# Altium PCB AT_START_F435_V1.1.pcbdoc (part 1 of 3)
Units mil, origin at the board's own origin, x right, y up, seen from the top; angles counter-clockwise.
Board outline 6521.81 x 4041.5 mil, 2 copper layers (Top Layer, Bottom Layer); 158 components, 212 nets, 714 pads, 868 vias.
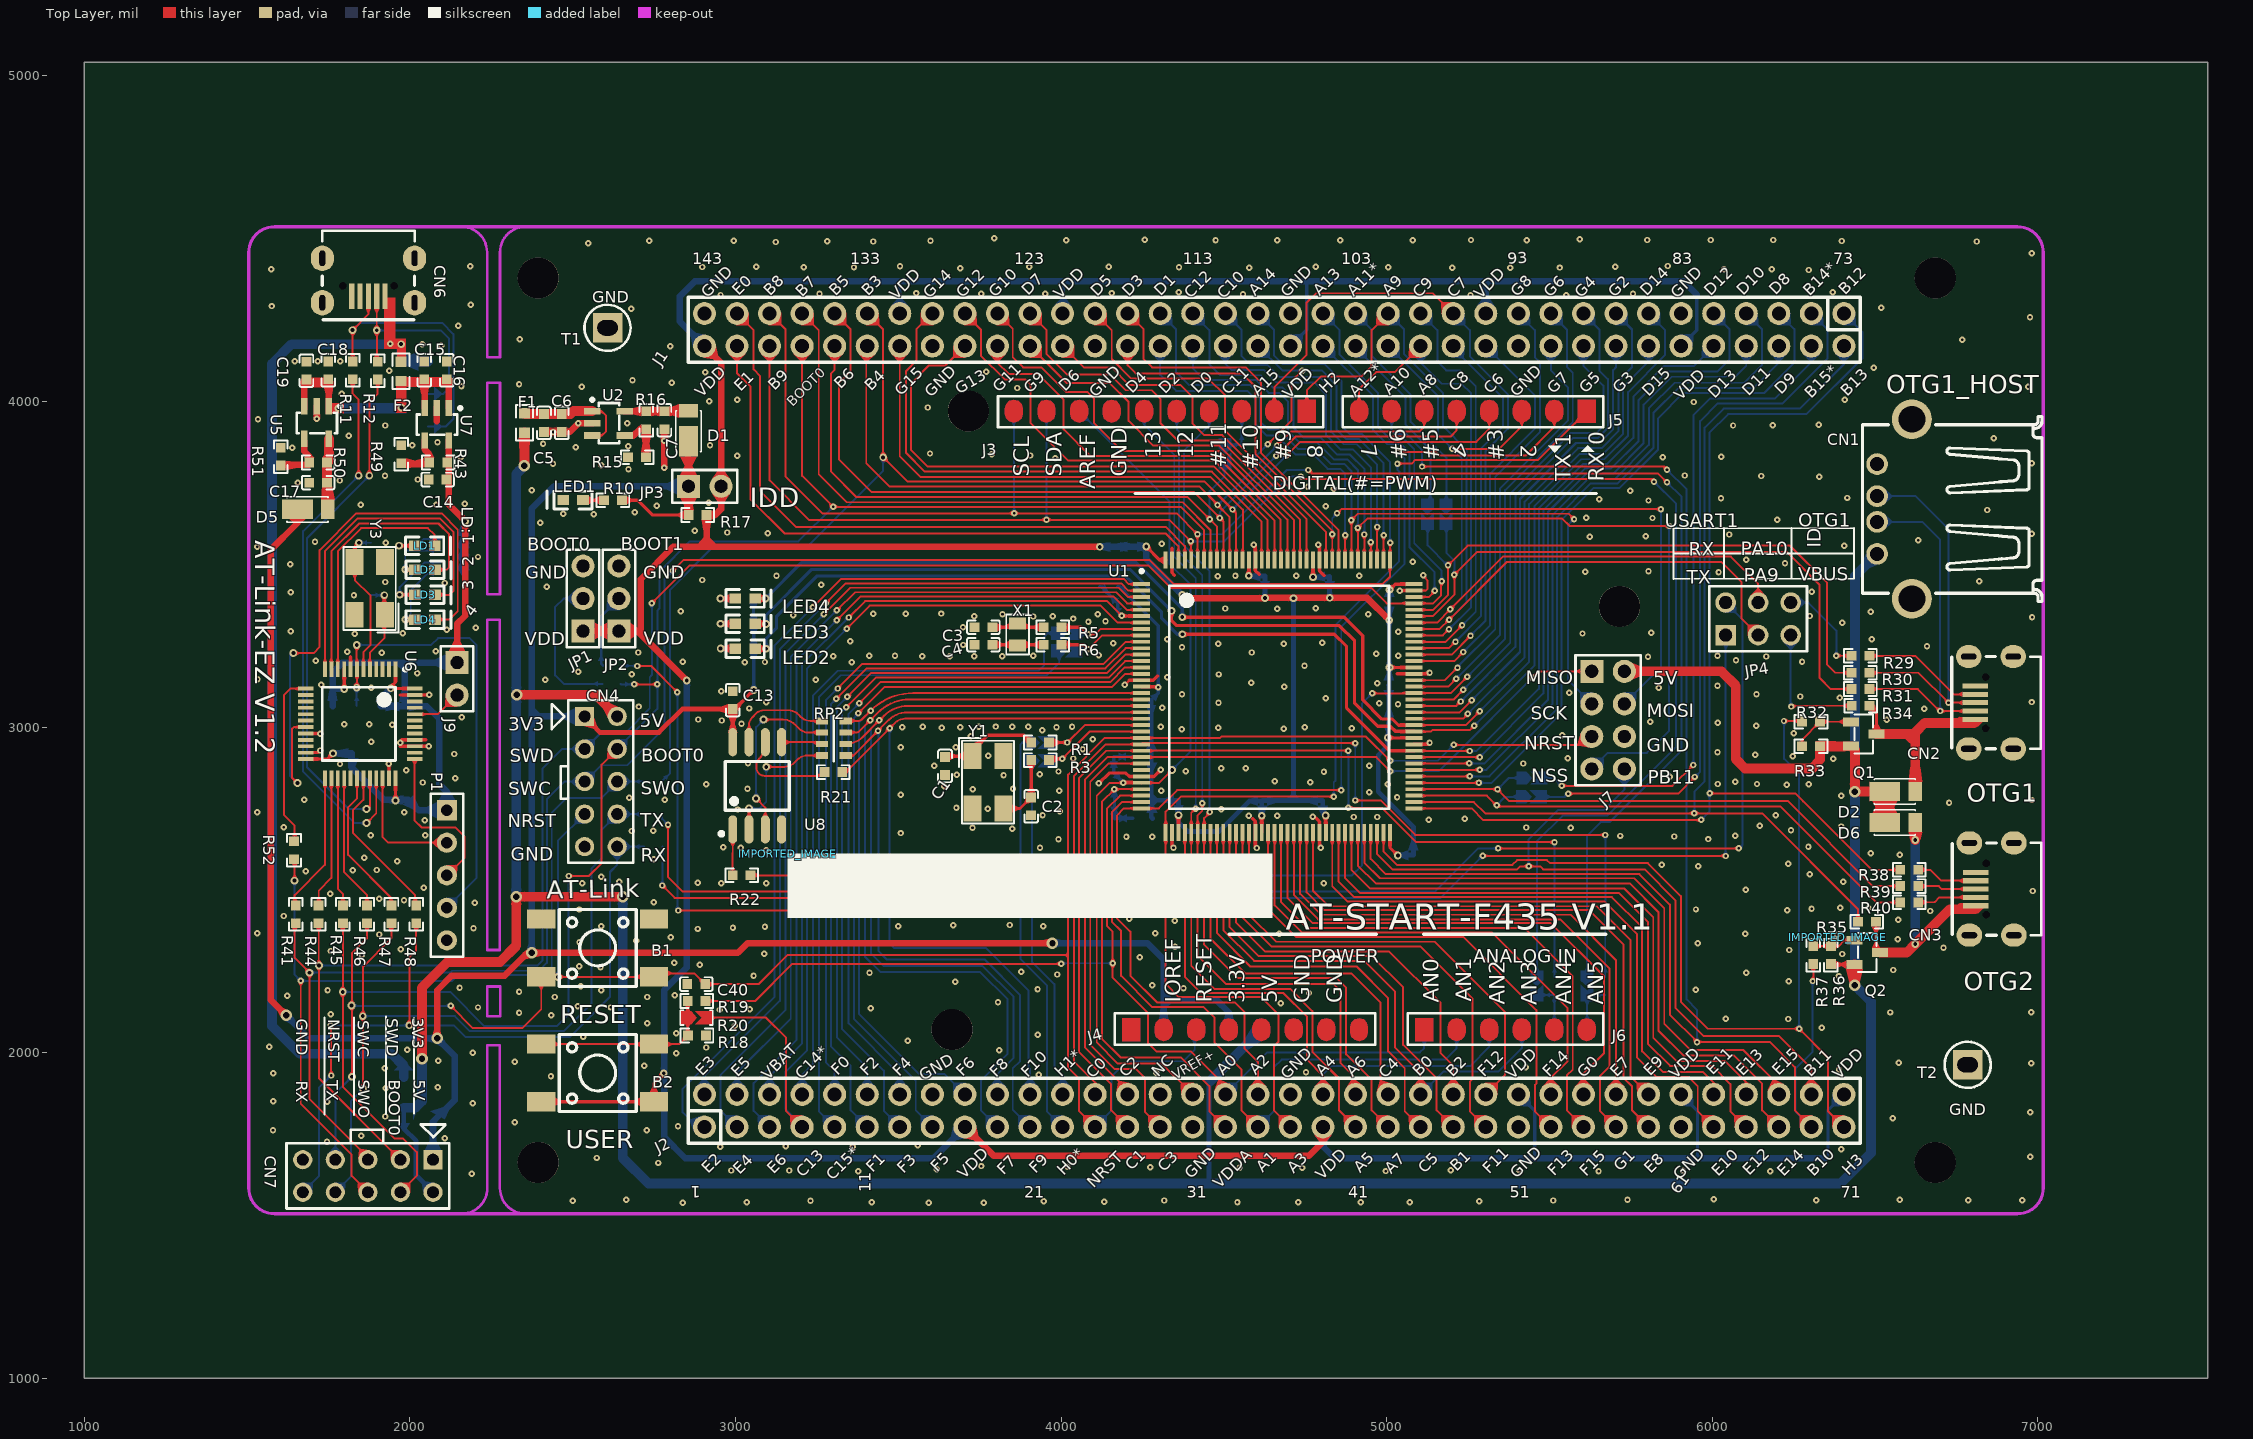
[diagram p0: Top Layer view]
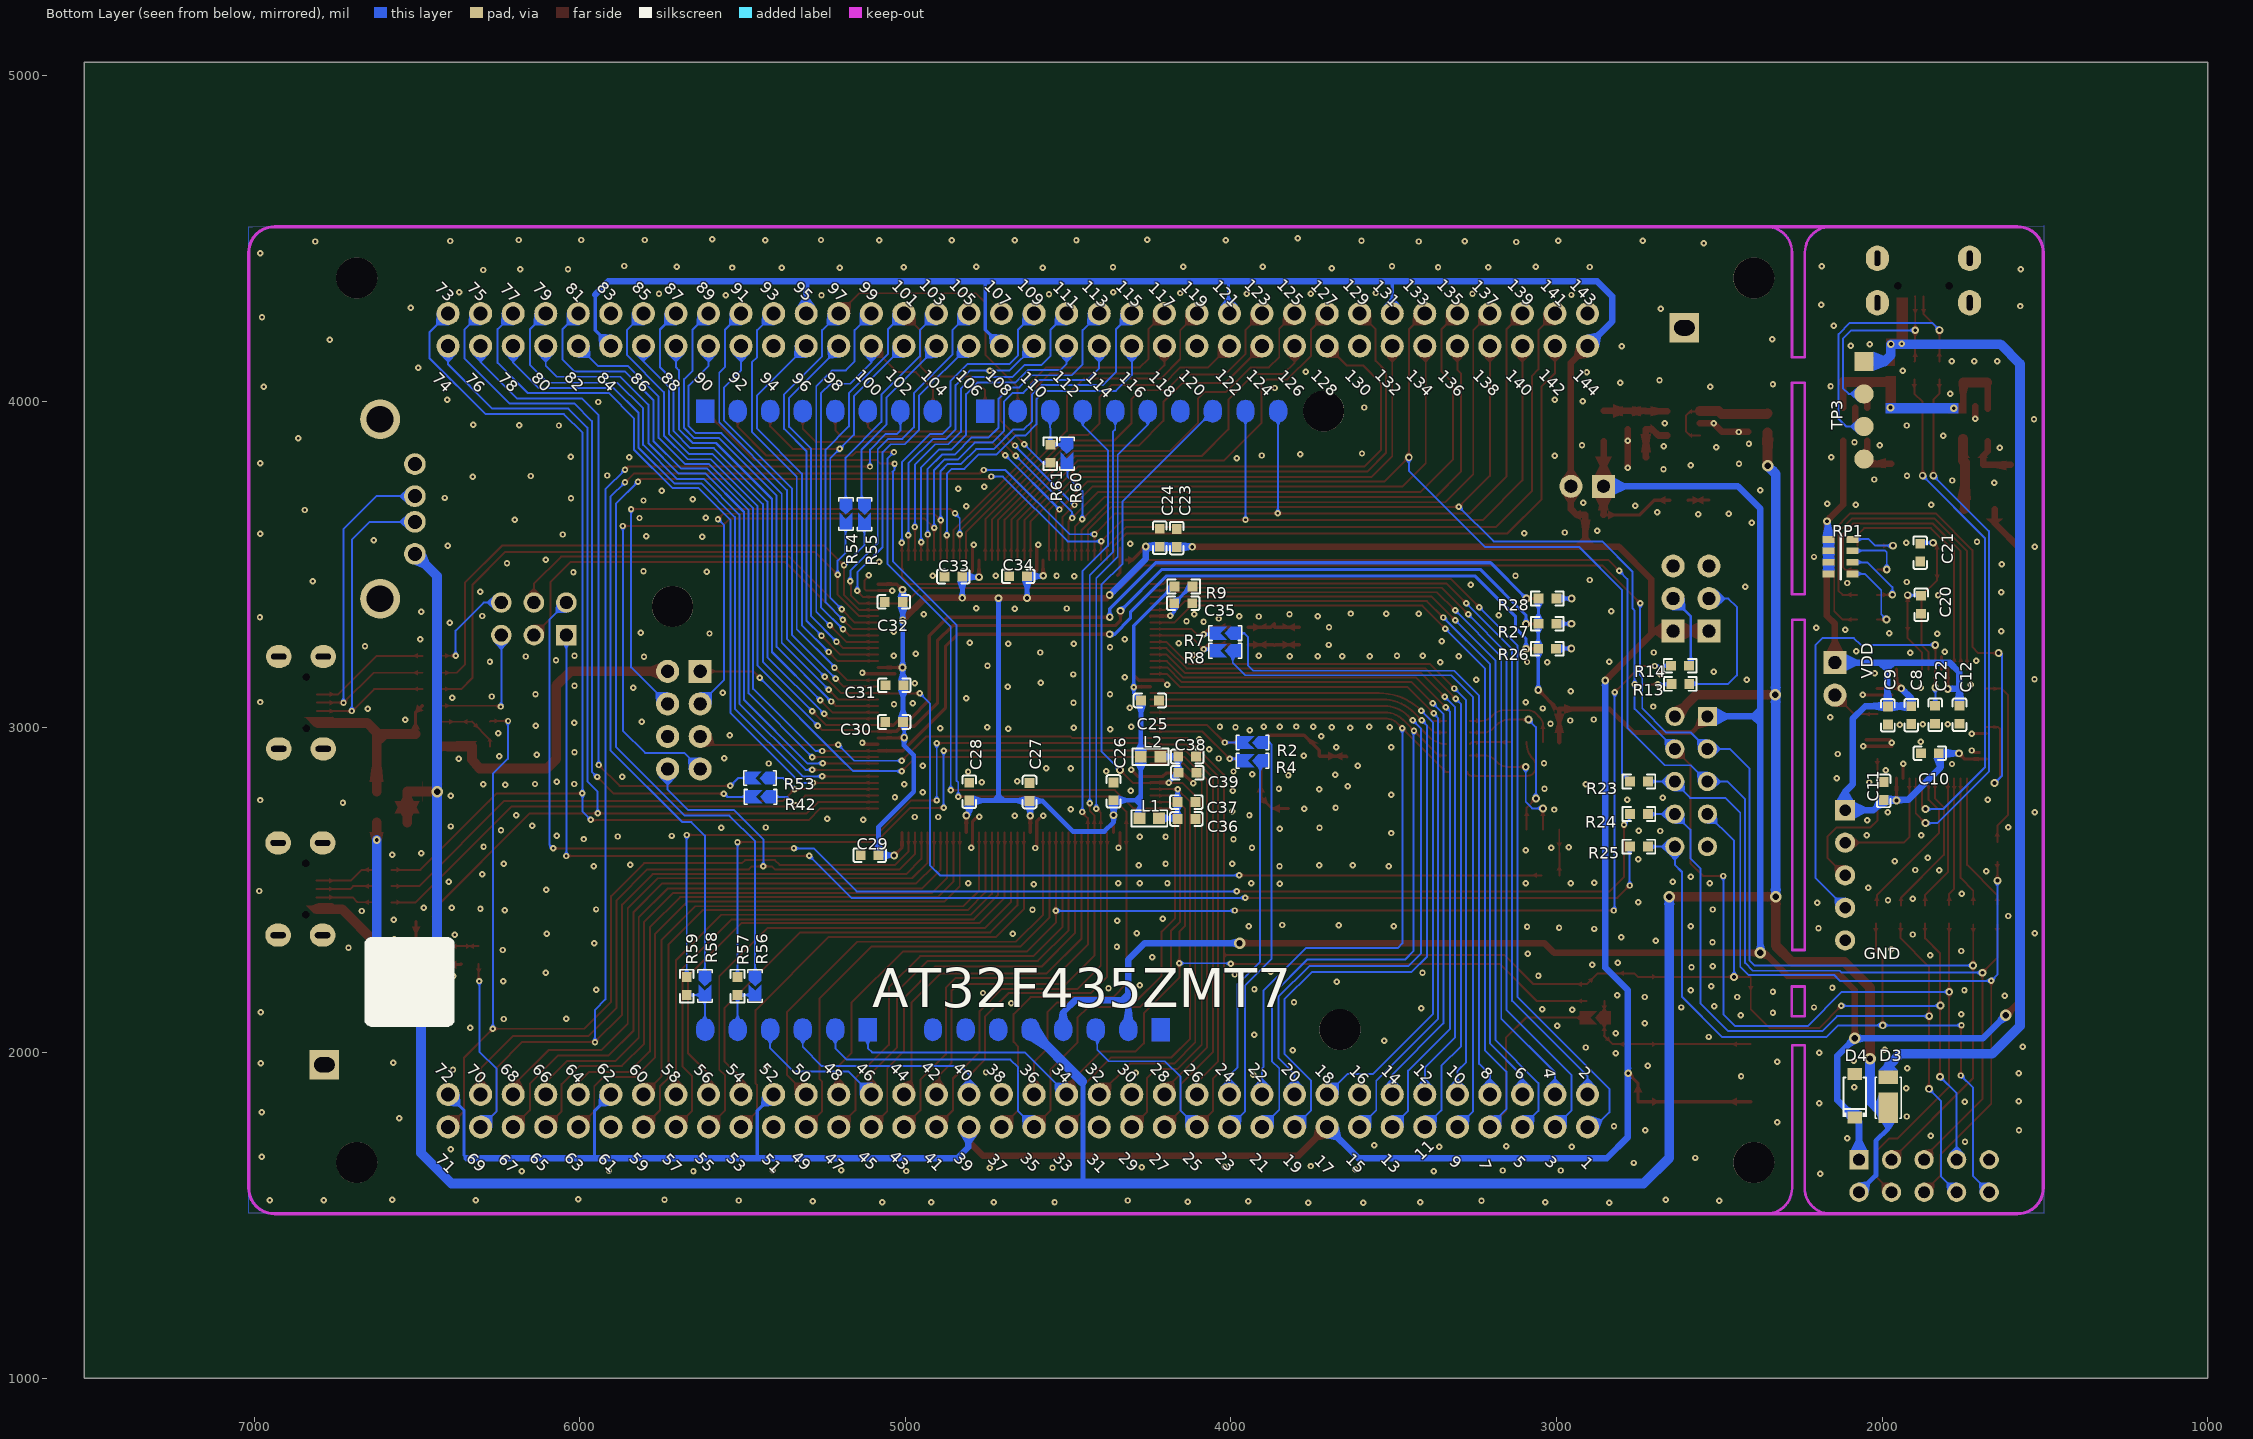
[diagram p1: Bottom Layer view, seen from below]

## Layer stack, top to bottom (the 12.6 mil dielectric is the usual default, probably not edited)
Top Layer: signal copper (thickness not stored)
Dielectric: dielectric 12.6, FR-4, Dk 4.8
Bottom Layer: signal copper (thickness not stored)

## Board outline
7521.81,1000 1000,1000 1000,5041.5 7521.81,5041.5

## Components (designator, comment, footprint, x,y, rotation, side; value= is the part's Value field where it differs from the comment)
B1 "贴片按键 6x6x5mm 黑色" SW-SMD_4P-L6.0-W6.0-P4.50-LS9.0 2576.69,2321.36 r180 top
B2 "贴片按键 6x6x5mm 蓝色" SW-SMD_4P-L6.0-W6.0-P4.50-LS9.0 2576.69,1937.36 r180 top
C1 "22pF" 0603_C-M#1 3643.64,2880.35 r270 top
C2 "22pF" 0603_C-M#1 3908.05,2756.34 r270 top
C3 "10pF" 0603_C-M#1 3761.68,3306.57 r180 top
C4 "10pF" 0603_C-M#1 3761.68,3252.78 r180 top
C5 "10uF" 0603_C-M#1 2411.64,3934 r90 top
C6 "0.1uF" 0603_C-M#1 2466.64,3934 r90 top
C7 "10uF" 0603_C-M#1 2781.64,3942.35 r90 top
C8 "4.7uF" 0603_C-M#2 1910.09,3036.57 r270 bottom
C9 "0.1uF" 0603_C-M#2 1982.09,3035.57 r270 bottom
C10 "0.1uF" 0603_C-M#2 1853.09,2919.57 r0 bottom
C11 "0.1uF" 0603_C-M#2 1995.09,2803.57 r90 bottom
C12 "0.1uF" 0603_C-M#2 1762.09,3037.57 r270 bottom
C13 "0.1uF" 0603_C-M#1 2991.55,3082.51 r270 top
C14 "10uF" 0603_C-M#1 2085,3760 r0 top
C15 "10uF" 0603_C-M#1 2044.09,4095.57 r270 top
C16 "0.1uF" 0603_C-M#1 2113.09,4095.57 r270 top
C17 "10uF" 0603_C-M#1 1718.09,3750.57 r0 top
C18 "10uF" 0603_C-M#1 1749.09,4095.57 r270 top
C19 "0.1uF" 0603_C-M#1 1682.09,4094.57 r270 top
C20 "22pF" 0603_C-M#2 1880.09,3375.57 r270 bottom
C21 "22pF" 0603_C-M#2 1883.09,3535.57 r90 bottom
C22 "0.1uF" 0603_C-M#2 1837.09,3037.57 r270 bottom
C23 "4.7uF" 0603_C-M#2 4166.64,3580.35 r90 bottom
C24 "0.1uF" 0603_C-M#2 4218.64,3581.35 r90 bottom
C25 "0.1uF" 0603_C-M#2 4248.64,3081.35 r180 bottom
C26 "0.1uF" 0603_C-M#2 4360.64,2802.35 r90 bottom
C27 "0.1uF" 0603_C-M#2 4618.64,2800.35 r90 bottom
C28 "0.1uF" 0603_C-M#2 4803.64,2801.35 r90 bottom
C29 "0.1uF" 0603_C-M#2 5109.64,2606.35 r0 bottom
C30 "0.1uF" 0603_C-M#2 5034.64,3015.35 r0 bottom
C31 "0.1uF" 0603_C-M#2 5033.64,3128.35 r0 bottom
C32 "0.1uF" 0603_C-M#2 5035.64,3384.35 r0 bottom
C33 "0.1uF" 0603_C-M#2 4852.64,3462.35 r0 bottom
C34 "0.1uF" 0603_C-M#2 4653.64,3463.35 r0 bottom
C35 "0.1uF" 0603_C-M#2 4146.64,3380.35 r180 bottom
C36 "1uF" 0603_C-M#2 4136.64,2717.35 r180 bottom
C37 "0.1uF" 0603_C-M#2 4136.64,2769.35 r180 bottom
C38 "0.1uF" 0603_C-M#2 4133.64,2859.35 r180 bottom
C39 "1uF" 0603_C-M#2 4134.64,2909.35 r180 bottom
C40 "0.1uF" 0603_C-M#1 2879.64,2210.35 r0 top
CN1 "JTJ-USB-AF-08" USB-A-TH__USB-AF-90 6560.06,3669.64 r90 top
CN2 "USB_micro B" USB_MIC_DIP 6807.49,3074.7 r0 top
CN3 "USB_micro B" USB_MIC_DIP 6809.35,2502.31 r0 top
CN4 "直插简易牛角2.54mm，2x5P" HDR2X5 2536.53,3032.54 r270 top
CN6 "USB_micro B" USB_MIC_DIP 1872.64,4322.58 r90 top
CN7 "直插简易牛角2.54mm，2x5P" HDR2X5 2070.89,1670.96 r180 top
D1 "DFLS130L-7" POWERDI-123_L2.8-W1.8-LS3.7-RD#1 2855.64,3924.36 r90 top
D2 "DFLS130L-7" POWERDI-123_L2.8-W1.8-LS3.7-RD#1 6577,2801.65 r0 top
D3 "DFLS130L-7" POWERDI-123_L2.8-W1.8-LS3.7-RD#2 1981.14,1877.57 r270 bottom
D4 "SMF3.3A" SOD-123_L2.8-W1.8-LS3.7-RD 2084.09,1867.57 r270 bottom
D5 "DFLS130L-7" POWERDI-123_L2.8-W1.8-LS3.7-RD#1 1701.14,3668.57 r0 top
D6 "DFLS130L-7" POWERDI-123_L2.8-W1.8-LS3.7-RD#1 6577,2706.31 r0 top
F1 "SMD0603B050TF" R0603 2351.69,3933.97 r90 top
F2 "SMD0603B050TF" R0603 1973.09,4092.57 r270 top
IMPORTED_IMAGE "IMPORTED_IMAGE" IMPORTED_IMAGE 6386,2354.75 r0 top
IMPORTED_IMAGE "IMPORTED_IMAGE" IMPORTED_IMAGE 3159.85,2610.64 r0 top
J1 "HDR 2X36" HDR_2.54_2X36 4654.61,4220.04 r180 top
J2 "HDR 2X36" HDR_2.54_2X36 4654.61,1821.46 r0 top
J3 "CON10" "FEMALE HEADER 1X10" 4305.23,3970.35 r0 top
J4 "CON8" "FEMALE HEADER 1X8" 4565.23,2070.35 r0 top
J5 "CON8" "FEMALE HEADER 1X8" 5265.23,3970.35 r180 top
J6 "CON6" "FEMALE HEADER 1X6" 5365.23,2070.35 r0 top
J7 "Header 4X2" HDR2X4 5630.23,3170.94 r270 top
J9 "Jumper 1x2P" HDR1X2 2144.89,3197.97 r270 top
JP1 "Jumper 1x3P" "HEADER 1X3" 2531.8,3294.55 r90 top
JP2 "Jumper 1x3P" "HEADER 1X3" 2641.8,3294.55 r90 top
JP3 "Jumper 1x2P" "HEADER 1X2" 2855.64,3739.35 r0 top
JP4 "Header 3X2" HDR2X3 6041.16,3282.33 r0 top
L1 "0.5A,600Ω@100Mhz" 0603_L 4250.69,2719.36 r0 bottom
L2 "0.5A,600Ω@100Mhz" 0603_L 4246.69,2908.36 r0 bottom
LD1 "RED" LED0603#1 2014.9,3556.81 r0 top
LD2 "GREEN" LED0603#1 2015.86,3482.72 r0 top
LD3 "BLUE" LED0603#1 2015.9,3405.81 r0 top
LD4 "YELLOW" LED0603#1 2015.86,3329.81 r0 top
LED1 "RED" LED0603#1 2531.64,3697.35 r180 top
LED2 "RED" LED0603#1 2999.32,3240.28 r0 top
LED3 "YELLOW" LED0603#2 2999.32,3317.01 r0 top
LED4 "GREEN" LED0603#2 2999.32,3394.62 r0 top
P1 "HDR-M-2.54_1x5" HDR-M-2.54_1X5 2113.59,2544.57 r270 top
Q1 "SI2301" SOT-23-3_L2.9-W1.3-P1.90-LS2.4-BR 6465.49,2978.57 r180 top
Q2 "SI2301" SOT-23-3_L2.9-W1.3-P1.90-LS2.4-BR 6476.49,2307.57 r180 top
R1 "0R" 0603_R-M#1 3935.64,2952.35 r180 top
R2 "NC" SB-PAD 3933.64,2952.35 r180 bottom
R3 "0R" 0603_R-M#1 3935.64,2898.35 r180 top
R4 "NC" SB-PAD 3933.64,2896.35 r180 bottom
R5 "0R" 0603_R-M#1 3974.24,3306.57 r180 top
R6 "0R" 0603_R-M#1 3974.24,3252.78 r180 top
R7 "NC" SB-PAD 4017.64,3288.35 r180 bottom
R8 "NC" SB-PAD 4017.64,3234.35 r180 bottom
R9 "0R" 0603_R-M#2 4145.63,3431.66 r0 bottom
R10 "1K" 0603_R-M#1 2623.69,3696.36 r0 top
R11 "22R" 0603_R-M#1 1824.09,4095.57 r90 top
R12 "22R" 0603_R-M#1 1901.09,4094.57 r90 top
R13 "10K" 0603_R-M#2 2619.64,3132.35 r0 bottom
R14 "10K" 0603_R-M#2 2620.64,3188.35 r0 bottom
R15 "15K" 0603_R-M#1 2697.64,3828.35 r0 top
R16 "51K" 0603_R-M#1 2725.64,3942.35 r270 top
R17 "0R" 0603_R-M#1 2883.64,3651.35 r180 top
R18 "100K" 0603_R-M#1 2881.64,2052.35 r0 top
R19 "0R" 0603_R-M#1 2880.64,2158.35 r180 top
R20 "NC" SB-PAD 2880.64,2107.35 r0 top
R21 "33R" 0603_R-M#1 3300.55,2861.51 r0 top
R22 "33R" 0603_R-M#1 3018.79,2544.37 r0 top
R23 "120R" 0603_R-M#2 2746.73,2832.78 r0 bottom
R24 "120R" 0603_R-M#2 2746.73,2732.7 r0 bottom
R25 "120R" 0603_R-M#2 2746.73,2632.63 r0 bottom
R26 "1K" 0603_R-M#2 3028.7,3240.28 r180 bottom
R27 "1K" 0603_R-M#2 3027.91,3317.01 r180 bottom
R28 "1K" 0603_R-M#2 3027.91,3394.62 r180 bottom
R29 "1K" 0603_R-M#1 6455.49,3218.7 r180 top
R30 "22R" 0603_R-M#1 6455.49,3166.7 r180 top
R31 "22R" 0603_R-M#1 6455.49,3116.7 r180 top
R32 "470R" 0603_R-M#1 6303.5,3016.56 r180 top
R33 "10K" 0603_R-M#1 6303.5,2940.56 r180 top
R34 "10K" 0603_R-M#3 6456.09,3065.26 r180 top
R35 "1K" 0603_R-M#1 6475.35,2401.74 r180 top
R36 "10K" 0603_R-M#1 6364.53,2299.58 r90 top
R37 "470R" 0603_R-M#1 6310.53,2299.58 r270 top
R38 "1K" 0603_R-M#1 6605.35,2561.31 r180 top
R39 "22R" 0603_R-M#1 6605.35,2511.31 r180 top
R40 "22R" 0603_R-M#1 6605.35,2461.31 r180 top
R41 "33R" 0603_R-M#1 1649.09,2424.56 r270 top
R42 "NC" SB-PAD 5444.64,2785.35 r180 bottom
R43 "47K" 0603_R-M#1 2087.09,3812.57 r180 top
R44 "33R" 0603_R-M#1 1719.09,2424.57 r270 top
R45 "33R" 0603_R-M#1 1794.09,2424.57 r270 top
R46 "33R" 0603_R-M#1 1868.09,2424.56 r270 top
R47 "33R" 0603_R-M#1 1943.09,2424.57 r270 top
R48 "33R" 0603_R-M#1 2019.09,2424.56 r270 top
R49 "15K" 0603_R-M#1 1973.09,3837.57 r270 top
R50 "51K" 0603_R-M#1 1718.09,3812.57 r180 top
R51 "15K" 0603_R-M#1 1603.09,3830.57 r270 top
R52 "33R" 0603_R-M#1 1644.09,2621.57 r270 top
R53 "NC" SB-PAD 5446.64,2843.35 r180 bottom
R54 "NC" SB-PAD 5182.64,3653.88 r90 bottom
R55 "NC" SB-PAD 5125.43,3653.48 r90 bottom
R56 "NC" SB-PAD 5461.64,2204.35 r90 bottom
R57 "0R" 0603_R-M#2 5515.64,2204.35 r270 bottom
R58 "NC" SB-PAD 5615.64,2204.35 r90 bottom
R59 "0R" 0603_R-M#2 5671.64,2204.35 r270 bottom
R60 "NC" SB-PAD 4503.61,3839.57 r90 bottom
R61 "0R" 0603_R-M#2 4554.64,3839.35 r90 bottom
RP1 "1K" 0603*4,8P4R#1 2164.09,3576.57 r90 bottom
RP2 "33R" 0603*4,8P4R#2 3338.72,2912.37 r90 top
T1 "TESTPOINT TP-5006" TESTHOOK 2606.9,4226.13 r0 top
T2 "TESTPOINT TP-5006" TESTHOOK 6784.64,1962.43 r0 top
TP3 "1X4P_2.54F" "HDR1X4 - TOP" 2055.44,4123.02 r270 bottom
U1 "AT32F437ZMT7" LQFP144_20*20 4665.69,3094.36 r0 top
U2 "RT9080N-08GJ5" SOT-23-5 2624.64,3870.35 r0 top
U5 "RT9080N-08GJ5" SOT-23-5 1651.09,3920.57 r270 top
U6 "AT32F403CGT6" "LQFP48 - 2" 1955.6,3177.01 r270 top
U7 "RT9080N-08GJ5" SOT-23-5 2019.86,3914.91 r270 top
U8 "EN25QH128A-104HIP" SOIC-8_208MIL 3066.59,2819.47 r0 top
X1 "32.768KHz" FC-12M_L2.0-W1.2 3866.28,3283.91 r90 top
Y1 "8MHz" OSC-SMD_4P-L5.0-W3.2-BL 3775.69,2830.36 r270 top
Y3 "8MHz" OSC-SMD_4P-L5.0-W3.2-BL 1876.49,3425.97 r90 top

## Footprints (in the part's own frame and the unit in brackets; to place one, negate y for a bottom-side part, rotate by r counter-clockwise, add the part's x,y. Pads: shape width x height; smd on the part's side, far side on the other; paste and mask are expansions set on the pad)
0603*4,8P4R#1 [mm]
  rect 0.55x0.95 smd paste+0 mask+0.051: 1(0,0) 4(-2.7,0) 5(-2.7,-1.85) 8(0,-1.85)
  rect 0.5x0.95 smd paste+0 mask+0.051: 2(-0.9,0) 3(-1.8,0) 6(-1.8,-1.85) 7(-0.9,-1.85)
  silkscreen extent -3.1,-0.94 0.43,-0.94
0603*4,8P4R#2 [mm]
  rect 0.55x0.95 smd paste+0 mask+0.051: 1(0,0) 4(2.7,0) 5(2.7,1.85) 8(0,1.85)
  rect 0.5x0.95 smd paste+0 mask+0.051: 2(0.9,0) 3(1.8,0) 6(1.8,1.85) 7(0.9,1.85)
  silkscreen extent -0.43,0.94 3.1,0.94
0603_C-M#1 [mil]
  rect 30x30 smd paste+0 mask+2: 1(27.5,0) 2(-27.5,0)
  silkscreen extent -50,-21 50,21
0603_C-M#2 [mil]
  rect 30x30 smd paste+0 mask+2: 1(-27.5,0) 2(27.5,0)
  silkscreen extent -50,-21 50,21
0603_L [mm]
  rect 0.93x0.9 smd paste+0 mask+0.051: 1(0.77,0) 2(-0.77,0)
  silkscreen extent -1.4,-0.64 1.4,0.64
0603_R-M#1 [mil]
  rect 30x30 smd paste+0 mask+2: 1(27.5,0) 2(-27.5,0)
  silkscreen extent -50,-21 50,21
0603_R-M#2 [mil]
  rect 30x30 smd paste+0 mask+2: 1(-27.5,0) 2(27.5,0)
  silkscreen extent -50,-21 50,21
0603_R-M#3 [mil]
  rect 30x30 smd paste+0 mask+4: 1(27.5,0) 2(-27.5,0)
  silkscreen extent -50,-21 50,21
FC-12M_L2.0-W1.2 [mm]
  rect 0.925x1.3 smd paste+0 mask+0.051: 1(-0.863,0) 2(0.863,0)
  silkscreen extent -1.55,-0.88 1.55,0.88
"FEMALE HEADER 1X6" [mil]
  Top Layer region: 277.55,-7.87 273.86,-21.65 263.78,-31.74 250,-35.43 236.22,-31.74 226.13,-21.65 222.44,-7.87 222.44,7.87 226.13,21.65 236.22,31.74 250,35.43 263.78,31.74 273.86,21.65 277.55,7.87
  Top Layer region: 177.55,-7.87 173.86,-21.65 163.78,-31.74 150,-35.43 136.22,-31.74 126.13,-21.65 122.44,-7.87 122.44,7.87 126.13,21.65 136.22,31.74 150,35.43 163.78,31.74 173.86,21.65 177.55,7.87
  Top Layer region: 77.55,-7.87 73.86,-21.65 63.78,-31.74 50,-35.43 36.22,-31.74 26.13,-21.65 22.44,-7.87 22.44,7.87 26.13,21.65 36.22,31.74 50,35.43 63.78,31.74 73.86,21.65 77.55,7.87
  Top Layer region: -22.45,-7.87 -26.14,-21.65 -36.22,-31.74 -50,-35.43 -63.78,-31.74 -73.87,-21.65 -77.56,-7.87 -77.56,7.87 -73.87,21.65 -63.78,31.74 -50,35.43 -36.22,31.74 -26.14,21.65 -22.45,7.87
  Top Layer region: -122.45,-7.87 -126.14,-21.65 -136.22,-31.74 -150,-35.43 -163.78,-31.74 -173.87,-21.65 -177.56,-7.87 -177.56,7.87 -173.87,21.65 -163.78,31.74 -150,35.43 -136.22,31.74 -126.14,21.65 -122.45,7.87
  Top Layer region: -277.56,35.43 -222.45,35.43 -222.45,-35.43 -277.56,-35.43
  Bottom Layer region: 277.55,-7.87 273.86,-21.65 263.78,-31.74 250,-35.43 236.22,-31.74 226.13,-21.65 222.44,-7.87 222.44,7.87 226.13,21.65 236.22,31.74 250,35.43 263.78,31.74 273.86,21.65 277.55,7.87
  Bottom Layer region: 177.55,-7.87 173.86,-21.65 163.78,-31.74 150,-35.43 136.22,-31.74 126.13,-21.65 122.44,-7.87 122.44,7.87 126.13,21.65 136.22,31.74 150,35.43 163.78,31.74 173.86,21.65 177.55,7.87
  Bottom Layer region: 77.55,-7.87 73.86,-21.65 63.78,-31.74 50,-35.43 36.22,-31.74 26.13,-21.65 22.44,-7.87 22.44,7.87 26.13,21.65 36.22,31.74 50,35.43 63.78,31.74 73.86,21.65 77.55,7.87
  Bottom Layer region: -22.45,-7.87 -26.14,-21.65 -36.22,-31.74 -50,-35.43 -63.78,-31.74 -73.87,-21.65 -77.56,-7.87 -77.56,7.87 -73.87,21.65 -63.78,31.74 -50,35.43 -36.22,31.74 -26.14,21.65 -22.45,7.87
  Bottom Layer region: -122.45,-7.87 -126.14,-21.65 -136.22,-31.74 -150,-35.43 -163.78,-31.74 -173.87,-21.65 -177.56,-7.87 -177.56,7.87 -173.87,21.65 -163.78,31.74 -150,35.43 -136.22,31.74 -126.14,21.65 -122.45,7.87
  Bottom Layer region: -277.56,35.43 -222.45,35.43 -222.45,-35.43 -277.56,-35.43
  Multi-Layer region: 277.55,-7.87 273.86,-21.65 263.78,-31.74 250,-35.43 236.22,-31.74 226.13,-21.65 222.44,-7.87 222.44,7.87 226.13,21.65 236.22,31.74 250,35.43 263.78,31.74 273.86,21.65 277.55,7.87
  Multi-Layer region: 177.55,-7.87 173.86,-21.65 163.78,-31.74 150,-35.43 136.22,-31.74 126.13,-21.65 122.44,-7.87 122.44,7.87 126.13,21.65 136.22,31.74 150,35.43 163.78,31.74 173.86,21.65 177.55,7.87
  Multi-Layer region: 77.55,-7.87 73.86,-21.65 63.78,-31.74 50,-35.43 36.22,-31.74 26.13,-21.65 22.44,-7.87 22.44,7.87 26.13,21.65 36.22,31.74 50,35.43 63.78,31.74 73.86,21.65 77.55,7.87
  Multi-Layer region: -22.45,-7.87 -26.14,-21.65 -36.22,-31.74 -50,-35.43 -63.78,-31.74 -73.87,-21.65 -77.56,-7.87 -77.56,7.87 -73.87,21.65 -63.78,31.74 -50,35.43 -36.22,31.74 -26.14,21.65 -22.45,7.87
  Multi-Layer region: -122.45,-7.87 -126.14,-21.65 -136.22,-31.74 -150,-35.43 -163.78,-31.74 -173.87,-21.65 -177.56,-7.87 -177.56,7.87 -173.87,21.65 -163.78,31.74 -150,35.43 -136.22,31.74 -126.14,21.65 -122.45,7.87
  Multi-Layer region: -277.56,35.43 -222.45,35.43 -222.45,-35.43 -277.56,-35.43
  silkscreen extent -300,-46 300,50
"FEMALE HEADER 1X8" [mil]
  Top Layer region: 377.55,-7.88 373.86,-21.65 363.77,-31.74 349.99,-35.43 336.22,-31.74 326.13,-21.65 322.44,-7.88 322.44,7.87 326.13,21.65 336.22,31.74 349.99,35.43 363.77,31.74 373.86,21.65 377.55,7.87
  Top Layer region: 277.55,-7.88 273.86,-21.65 263.77,-31.74 249.99,-35.43 236.22,-31.74 226.13,-21.65 222.44,-7.88 222.44,7.87 226.13,21.65 236.22,31.74 249.99,35.43 263.77,31.74 273.86,21.65 277.55,7.87
  Top Layer region: 177.55,-7.88 173.86,-21.65 163.77,-31.74 149.99,-35.43 136.22,-31.74 126.13,-21.65 122.44,-7.88 122.44,7.87 126.13,21.65 136.22,31.74 149.99,35.43 163.77,31.74 173.86,21.65 177.55,7.87
  Top Layer region: 77.55,-7.88 73.86,-21.65 63.77,-31.74 49.99,-35.43 36.22,-31.74 26.13,-21.65 22.44,-7.88 22.44,7.87 26.13,21.65 36.22,31.74 49.99,35.43 63.77,31.74 73.86,21.65 77.55,7.87
  Top Layer region: -22.45,-7.88 -26.14,-21.65 -36.23,-31.74 -50.01,-35.43 -63.78,-31.74 -73.87,-21.65 -77.56,-7.88 -77.56,7.87 -73.87,21.65 -63.78,31.74 -50.01,35.43 -36.23,31.74 -26.14,21.65 -22.45,7.87
  Top Layer region: -122.45,-7.88 -126.14,-21.65 -136.23,-31.74 -150.01,-35.43 -163.78,-31.74 -173.87,-21.65 -177.56,-7.88 -177.56,7.87 -173.87,21.65 -163.78,31.74 -150.01,35.43 -136.23,31.74 -126.14,21.65 -122.45,7.87
  Top Layer region: -222.45,-7.88 -226.14,-21.65 -236.23,-31.74 -250.01,-35.43 -263.78,-31.74 -273.87,-21.65 -277.56,-7.88 -277.56,7.87 -273.87,21.65 -263.78,31.74 -250.01,35.43 -236.23,31.74 -226.14,21.65 -222.45,7.87
  Top Layer region: -377.56,35.43 -322.45,35.43 -322.45,-35.43 -377.56,-35.43
  Bottom Layer region: 377.55,-7.88 373.86,-21.65 363.77,-31.74 349.99,-35.43 336.22,-31.74 326.13,-21.65 322.44,-7.88 322.44,7.87 326.13,21.65 336.22,31.74 349.99,35.43 363.77,31.74 373.86,21.65 377.55,7.87
  Bottom Layer region: 277.55,-7.88 273.86,-21.65 263.77,-31.74 249.99,-35.43 236.22,-31.74 226.13,-21.65 222.44,-7.88 222.44,7.87 226.13,21.65 236.22,31.74 249.99,35.43 263.77,31.74 273.86,21.65 277.55,7.87
  Bottom Layer region: 177.55,-7.88 173.86,-21.65 163.77,-31.74 149.99,-35.43 136.22,-31.74 126.13,-21.65 122.44,-7.88 122.44,7.87 126.13,21.65 136.22,31.74 149.99,35.43 163.77,31.74 173.86,21.65 177.55,7.87
  Bottom Layer region: 77.55,-7.88 73.86,-21.65 63.77,-31.74 49.99,-35.43 36.22,-31.74 26.13,-21.65 22.44,-7.88 22.44,7.87 26.13,21.65 36.22,31.74 49.99,35.43 63.77,31.74 73.86,21.65 77.55,7.87
  Bottom Layer region: -22.45,-7.88 -26.14,-21.65 -36.23,-31.74 -50.01,-35.43 -63.78,-31.74 -73.87,-21.65 -77.56,-7.88 -77.56,7.87 -73.87,21.65 -63.78,31.74 -50.01,35.43 -36.23,31.74 -26.14,21.65 -22.45,7.87
  Bottom Layer region: -122.45,-7.88 -126.14,-21.65 -136.23,-31.74 -150.01,-35.43 -163.78,-31.74 -173.87,-21.65 -177.56,-7.88 -177.56,7.87 -173.87,21.65 -163.78,31.74 -150.01,35.43 -136.23,31.74 -126.14,21.65 -122.45,7.87
  Bottom Layer region: -222.45,-7.88 -226.14,-21.65 -236.23,-31.74 -250.01,-35.43 -263.78,-31.74 -273.87,-21.65 -277.56,-7.88 -277.56,7.87 -273.87,21.65 -263.78,31.74 -250.01,35.43 -236.23,31.74 -226.14,21.65 -222.45,7.87
  Bottom Layer region: -377.56,35.43 -322.45,35.43 -322.45,-35.43 -377.56,-35.43
  Multi-Layer region: 377.55,-7.88 373.86,-21.65 363.77,-31.74 349.99,-35.43 336.22,-31.74 326.13,-21.65 322.44,-7.88 322.44,7.87 326.13,21.65 336.22,31.74 349.99,35.43 363.77,31.74 373.86,21.65 377.55,7.87
  Multi-Layer region: 277.55,-7.88 273.86,-21.65 263.77,-31.74 249.99,-35.43 236.22,-31.74 226.13,-21.65 222.44,-7.88 222.44,7.87 226.13,21.65 236.22,31.74 249.99,35.43 263.77,31.74 273.86,21.65 277.55,7.87
  Multi-Layer region: 177.55,-7.88 173.86,-21.65 163.77,-31.74 149.99,-35.43 136.22,-31.74 126.13,-21.65 122.44,-7.88 122.44,7.87 126.13,21.65 136.22,31.74 149.99,35.43 163.77,31.74 173.86,21.65 177.55,7.87
  Multi-Layer region: 77.55,-7.88 73.86,-21.65 63.77,-31.74 49.99,-35.43 36.22,-31.74 26.13,-21.65 22.44,-7.88 22.44,7.87 26.13,21.65 36.22,31.74 49.99,35.43 63.77,31.74 73.86,21.65 77.55,7.87
  Multi-Layer region: -22.45,-7.88 -26.14,-21.65 -36.23,-31.74 -50.01,-35.43 -63.78,-31.74 -73.87,-21.65 -77.56,-7.88 -77.56,7.87 -73.87,21.65 -63.78,31.74 -50.01,35.43 -36.23,31.74 -26.14,21.65 -22.45,7.87
  Multi-Layer region: -122.45,-7.88 -126.14,-21.65 -136.23,-31.74 -150.01,-35.43 -163.78,-31.74 -173.87,-21.65 -177.56,-7.88 -177.56,7.87 -173.87,21.65 -163.78,31.74 -150.01,35.43 -136.23,31.74 -126.14,21.65 -122.45,7.87
  Multi-Layer region: -222.45,-7.88 -226.14,-21.65 -236.23,-31.74 -250.01,-35.43 -263.78,-31.74 -273.87,-21.65 -277.56,-7.88 -277.56,7.87 -273.87,21.65 -263.78,31.74 -250.01,35.43 -236.23,31.74 -226.14,21.65 -222.45,7.87
  Multi-Layer region: -377.56,35.43 -322.45,35.43 -322.45,-35.43 -377.56,-35.43
  silkscreen extent -400,-46 400,50
"FEMALE HEADER 1X10" [mil]
  Top Layer region: -477.56,7.87 -473.87,21.65 -463.78,31.74 -450.01,35.43 -436.23,31.74 -426.14,21.65 -422.45,7.87 -422.45,-7.88 -426.14,-21.65 -436.23,-31.74 -450.01,-35.43 -463.78,-31.74 -473.87,-21.65 -477.56,-7.88
  Top Layer region: -377.56,7.87 -373.87,21.65 -363.78,31.74 -350.01,35.43 -336.23,31.74 -326.14,21.65 -322.45,7.87 -322.45,-7.88 -326.14,-21.65 -336.23,-31.74 -350.01,-35.43 -363.78,-31.74 -373.87,-21.65 -377.56,-7.88
  Top Layer region: -277.56,7.87 -273.87,21.65 -263.78,31.74 -250.01,35.43 -236.23,31.74 -226.14,21.65 -222.45,7.87 -222.45,-7.88 -226.14,-21.65 -236.23,-31.74 -250.01,-35.43 -263.78,-31.74 -273.87,-21.65 -277.56,-7.88
  Top Layer region: -177.56,7.87 -173.87,21.65 -163.78,31.74 -150.01,35.43 -136.23,31.74 -126.14,21.65 -122.45,7.87 -122.45,-7.88 -126.14,-21.65 -136.23,-31.74 -150.01,-35.43 -163.78,-31.74 -173.87,-21.65 -177.56,-7.88
  Top Layer region: -77.56,7.87 -73.87,21.65 -63.78,31.74 -50.01,35.43 -36.23,31.74 -26.14,21.65 -22.45,7.87 -22.45,-7.88 -26.14,-21.65 -36.23,-31.74 -50.01,-35.43 -63.78,-31.74 -73.87,-21.65 -77.56,-7.88
  Top Layer region: 22.44,7.87 26.13,21.65 36.22,31.74 49.99,35.43 63.77,31.74 73.86,21.65 77.55,7.87 77.55,-7.88 73.86,-21.65 63.77,-31.74 49.99,-35.43 36.22,-31.74 26.13,-21.65 22.44,-7.88
  Top Layer region: 122.44,7.87 126.13,21.65 136.22,31.74 149.99,35.43 163.77,31.74 173.86,21.65 177.55,7.87 177.55,-7.88 173.86,-21.65 163.77,-31.74 149.99,-35.43 136.22,-31.74 126.13,-21.65 122.44,-7.88
  Top Layer region: 222.44,7.87 226.13,21.65 236.22,31.74 249.99,35.43 263.77,31.74 273.86,21.65 277.55,7.87 277.55,-7.88 273.86,-21.65 263.77,-31.74 249.99,-35.43 236.22,-31.74 226.13,-21.65 222.44,-7.88
  Top Layer region: 322.44,7.87 326.13,21.65 336.22,31.74 349.99,35.43 363.77,31.74 373.86,21.65 377.55,7.87 377.55,-7.88 373.86,-21.65 363.77,-31.74 349.99,-35.43 336.22,-31.74 326.13,-21.65 322.44,-7.88
  Top Layer region: 477.55,-35.43 422.44,-35.43 422.44,35.43 477.55,35.43
  Bottom Layer region: -477.56,7.87 -473.87,21.65 -463.78,31.74 -450.01,35.43 -436.23,31.74 -426.14,21.65 -422.45,7.87 -422.45,-7.88 -426.14,-21.65 -436.23,-31.74 -450.01,-35.43 -463.78,-31.74 -473.87,-21.65 -477.56,-7.88
  Bottom Layer region: -377.56,7.87 -373.87,21.65 -363.78,31.74 -350.01,35.43 -336.23,31.74 -326.14,21.65 -322.45,7.87 -322.45,-7.88 -326.14,-21.65 -336.23,-31.74 -350.01,-35.43 -363.78,-31.74 -373.87,-21.65 -377.56,-7.88
  Bottom Layer region: -277.56,7.87 -273.87,21.65 -263.78,31.74 -250.01,35.43 -236.23,31.74 -226.14,21.65 -222.45,7.87 -222.45,-7.88 -226.14,-21.65 -236.23,-31.74 -250.01,-35.43 -263.78,-31.74 -273.87,-21.65 -277.56,-7.88
  Bottom Layer region: -177.56,7.87 -173.87,21.65 -163.78,31.74 -150.01,35.43 -136.23,31.74 -126.14,21.65 -122.45,7.87 -122.45,-7.88 -126.14,-21.65 -136.23,-31.74 -150.01,-35.43 -163.78,-31.74 -173.87,-21.65 -177.56,-7.88
  Bottom Layer region: -77.56,7.87 -73.87,21.65 -63.78,31.74 -50.01,35.43 -36.23,31.74 -26.14,21.65 -22.45,7.87 -22.45,-7.88 -26.14,-21.65 -36.23,-31.74 -50.01,-35.43 -63.78,-31.74 -73.87,-21.65 -77.56,-7.88
  Bottom Layer region: 22.44,7.87 26.13,21.65 36.22,31.74 49.99,35.43 63.77,31.74 73.86,21.65 77.55,7.87 77.55,-7.88 73.86,-21.65 63.77,-31.74 49.99,-35.43 36.22,-31.74 26.13,-21.65 22.44,-7.88
  Bottom Layer region: 122.44,7.87 126.13,21.65 136.22,31.74 149.99,35.43 163.77,31.74 173.86,21.65 177.55,7.87 177.55,-7.88 173.86,-21.65 163.77,-31.74 149.99,-35.43 136.22,-31.74 126.13,-21.65 122.44,-7.88
  Bottom Layer region: 222.44,7.87 226.13,21.65 236.22,31.74 249.99,35.43 263.77,31.74 273.86,21.65 277.55,7.87 277.55,-7.88 273.86,-21.65 263.77,-31.74 249.99,-35.43 236.22,-31.74 226.13,-21.65 222.44,-7.88
  Bottom Layer region: 322.44,7.87 326.13,21.65 336.22,31.74 349.99,35.43 363.77,31.74 373.86,21.65 377.55,7.87 377.55,-7.88 373.86,-21.65 363.77,-31.74 349.99,-35.43 336.22,-31.74 326.13,-21.65 322.44,-7.88
  Bottom Layer region: 477.55,-35.43 422.44,-35.43 422.44,35.43 477.55,35.43
  Multi-Layer region: -477.56,7.87 -473.87,21.65 -463.78,31.74 -450.01,35.43 -436.23,31.74 -426.14,21.65 -422.45,7.87 -422.45,-7.88 -426.14,-21.65 -436.23,-31.74 -450.01,-35.43 -463.78,-31.74 -473.87,-21.65 -477.56,-7.88
  Multi-Layer region: -377.56,7.87 -373.87,21.65 -363.78,31.74 -350.01,35.43 -336.23,31.74 -326.14,21.65 -322.45,7.87 -322.45,-7.88 -326.14,-21.65 -336.23,-31.74 -350.01,-35.43 -363.78,-31.74 -373.87,-21.65 -377.56,-7.88
  Multi-Layer region: -277.56,7.87 -273.87,21.65 -263.78,31.74 -250.01,35.43 -236.23,31.74 -226.14,21.65 -222.45,7.87 -222.45,-7.88 -226.14,-21.65 -236.23,-31.74 -250.01,-35.43 -263.78,-31.74 -273.87,-21.65 -277.56,-7.88
  Multi-Layer region: -177.56,7.87 -173.87,21.65 -163.78,31.74 -150.01,35.43 -136.23,31.74 -126.14,21.65 -122.45,7.87 -122.45,-7.88 -126.14,-21.65 -136.23,-31.74 -150.01,-35.43 -163.78,-31.74 -173.87,-21.65 -177.56,-7.88
  Multi-Layer region: -77.56,7.87 -73.87,21.65 -63.78,31.74 -50.01,35.43 -36.23,31.74 -26.14,21.65 -22.45,7.87 -22.45,-7.88 -26.14,-21.65 -36.23,-31.74 -50.01,-35.43 -63.78,-31.74 -73.87,-21.65 -77.56,-7.88
  Multi-Layer region: 22.44,7.87 26.13,21.65 36.22,31.74 49.99,35.43 63.77,31.74 73.86,21.65 77.55,7.87 77.55,-7.88 73.86,-21.65 63.77,-31.74 49.99,-35.43 36.22,-31.74 26.13,-21.65 22.44,-7.88
  Multi-Layer region: 122.44,7.87 126.13,21.65 136.22,31.74 149.99,35.43 163.77,31.74 173.86,21.65 177.55,7.87 177.55,-7.88 173.86,-21.65 163.77,-31.74 149.99,-35.43 136.22,-31.74 126.13,-21.65 122.44,-7.88
  Multi-Layer region: 222.44,7.87 226.13,21.65 236.22,31.74 249.99,35.43 263.77,31.74 273.86,21.65 277.55,7.87 277.55,-7.88 273.86,-21.65 263.77,-31.74 249.99,-35.43 236.22,-31.74 226.13,-21.65 222.44,-7.88
  Multi-Layer region: 322.44,7.87 326.13,21.65 336.22,31.74 349.99,35.43 363.77,31.74 373.86,21.65 377.55,7.87 377.55,-7.88 373.86,-21.65 363.77,-31.74 349.99,-35.43 336.22,-31.74 326.13,-21.65 322.44,-7.88
  Multi-Layer region: 477.55,-35.43 422.44,-35.43 422.44,35.43 477.55,35.43
  silkscreen extent -499,-50 500,46
HDR1X2 [mm]
  rect 1.8x1.8 hole 1 slot 1.005 at 0 deg paste+0 mask+0.051: 1(0,0)
  round 1.8 hole 1 slot 1.005 at 0 deg paste+0 mask+0.051: 2(2.54,0)
  silkscreen extent -1.27,-1.27 3.81,1.27
"HDR1X4 - TOP" [mm]
  rect 1.5x1.5 smd paste+0 mask+0.051: 1(0,0)
  round 1.5 smd paste+0 mask+0.051: 2(2.54,0) 3(5.08,0) 4(7.62,0)
HDR2X3 [mm]
  rect 1.6x1.6 hole 1 slot 1.005 at 0 deg paste+0 mask+0.051: 1(0,0)
  round 1.6 hole 1 slot 1.005 at 0 deg paste+0 mask+0.051: 2(0,2.54) 3(2.54,0) 4(2.54,2.54) 5(5.08,0) 6(5.08,2.54)
  silkscreen extent -1.27,-1.27 6.35,3.81
HDR2X4 [mm]
  rect 1.8x1.8 hole 1 slot 1.005 at 0 deg paste+0 mask+0.051: 1(0,0)
  round 1.8 hole 1 slot 1.005 at 0 deg paste+0 mask+0.051: 2(0,2.54) 3(2.54,0) 4(2.54,2.54) 5(5.08,0) 6(5.08,2.54) 7(7.62,0) 8(7.62,2.54)
  silkscreen extent -1.27,-1.27 8.89,3.81
HDR2X5 [mm]
  rect 1.5x1.5 hole 0.9 slot 0.905 at 0 deg paste+0 mask+0.051: 1(0,0)
  round 1.5 hole 0.9 slot 0.905 at 0 deg paste+0 mask+0.051: 2(0,2.54) 3(2.54,0) 4(2.54,2.54) 5(5.08,0) 6(5.08,2.54) 7(7.62,0) 8(7.62,2.54) 9(10.16,0) 10(10.16,2.54)
  silkscreen extent -1.27,-1.27 11.43,3.81
HDR-M-2.54_1X5 [mil]
  rect 62x62 hole 35 paste+0 mask+2: 1(-200,0)
  round 62 hole 35 paste+0 mask+2: 2(-100,0) 3(0,0) 4(100,0) 5(200,0)
  silkscreen extent -250,-50 250,50
HDR_2.54_2X36 [mm]
  round 1.8 hole 1.1 paste+0 mask+0.051: 1(-44.45,-1.27) 2(-44.45,1.27) 3(-41.91,-1.27) 4(-41.91,1.27) 5(-39.37,-1.27) 6(-39.37,1.27) 7(-36.83,-1.27) 8(-36.83,1.27) 9(-34.29,-1.27) 10(-34.29,1.27) 11(-31.75,-1.27) 12(-31.75,1.27) 13(-29.21,-1.27) 14(-29.21,1.27) 15(-26.67,-1.27) 16(-26.67,1.27) 17(-24.13,-1.27) 18(-24.13,1.27) 19(-21.59,-1.27) 20(-21.59,1.27) 21(-19.05,-1.27) 22(-19.05,1.27) 23(-16.51,-1.27) 24(-16.51,1.27) 25(-13.97,-1.27) 26(-13.97,1.27) 27(-11.43,-1.27) 28(-11.43,1.27) 29(-8.89,-1.27) 30(-8.89,1.27) 31(-6.35,-1.27) 32(-6.35,1.27) 33(-3.81,-1.27) 34(-3.81,1.27) 35(-1.27,-1.27) 36(-1.27,1.27) 37(1.27,-1.27) 38(1.27,1.27) 39(3.81,-1.27) 40(3.81,1.27) 41(6.35,-1.27) 42(6.35,1.27) 43(8.89,-1.27) 44(8.89,1.27) 45(11.43,-1.27) 46(11.43,1.27) 47(13.97,-1.27) 48(13.97,1.27) 49(16.51,-1.27) 50(16.51,1.27) 51(19.05,-1.27) 52(19.05,1.27) 53(21.59,-1.27) 54(21.59,1.27) 55(24.13,-1.27) 56(24.13,1.27) 57(26.67,-1.27) 58(26.67,1.27) 59(29.21,-1.27) 60(29.21,1.27) 61(31.75,-1.27) 62(31.75,1.27) 63(34.29,-1.27) 64(34.29,1.27) 65(36.83,-1.27) 66(36.83,1.27) 67(39.37,-1.27) 68(39.37,1.27) 69(41.91,-1.27) 70(41.91,1.27) 71(44.45,-1.27) 72(44.45,1.27)
  silkscreen extent -45.72,-2.54 45.72,2.54
"HEADER 1X2" [mm]
  rect 1.8x1.8 hole 1 slot 1.005 at 0 deg paste+0 mask+0.051: 1(0,0)
  round 1.8 hole 1 slot 1.005 at 0 deg paste+0 mask+0.051: 2(2.54,0)
  silkscreen extent -1.27,-1.27 3.81,1.27
"HEADER 1X3" [mm]
  rect 1.8x1.8 hole 1 slot 1.005 at 0 deg paste+0 mask+0.051: 1(0,0)
  round 1.8 hole 1 slot 1.005 at 0 deg paste+0 mask+0.051: 2(2.54,0) 3(5.08,0)
  silkscreen extent -1.27,-1.27 6.35,1.27
IMPORTED_IMAGE [mil]
LED0603#1 [mil]
  rect 36x32 smd paste+0 mask+2: 1(-0.04,0.2) 2(60.96,0.2)
  silkscreen extent -28,-28 110,27
LED0603#2 [mil]
  rect 36x32 smd paste+0 mask+4: 1(-0.04,0.2) 2(60.96,0.2)
  silkscreen extent -28,-28 110,27
"LQFP48 - 2" [mm]
  rect 1.2x0.3 smd paste+0 mask+0.051: 1(0,0) 2(0,-0.5) 3(0,-1) 4(0,-1.5) 5(0,-2) 6(0,-2.5) 7(0,-3) 8(0,-3.5) 9(0,-4) 10(0,-4.5) 11(0,-5) 12(0,-5.5) 25(8.5,-5.5) 26(8.5,-5) 27(8.5,-4.5) 28(8.5,-4) 29(8.5,-3.5) 30(8.5,-3) 31(8.5,-2.5) 32(8.5,-2) 33(8.5,-1.5) 34(8.5,-1) 35(8.5,-0.5) 36(8.5,0)
  rect 0.3x1.2 smd paste+0 mask+0.051: 13(1.5,-7) 14(2,-7) 15(2.5,-7) 16(3,-7) 17(3.5,-7) 18(4,-7) 19(4.5,-7) 20(5,-7) 21(5.5,-7) 22(6,-7) 23(6.5,-7) 24(7,-7) 37(7,1.5) 38(6.5,1.5) 39(6,1.5) 40(5.5,1.5) 41(5,1.5) 42(4.5,1.5) 43(4,1.5) 44(3.5,1.5) 45(3,1.5) 46(2.5,1.5) 47(2,1.5) 48(1.5,1.5)
  silkscreen extent -0.12,-5.71 7.11,0.89
LQFP144_20*20 [mm]
  rect 1.35x0.3 smd paste+0 mask+0.102: 1(-10.625,8.75) 2(-10.625,8.25) 3(-10.625,7.75) 4(-10.625,7.25) 5(-10.625,6.75) 6(-10.625,6.25) 7(-10.625,5.75) 8(-10.625,5.25) 9(-10.625,4.75) 10(-10.625,4.25) 11(-10.625,3.75) 12(-10.625,3.25) 13(-10.625,2.75) 14(-10.625,2.25) 15(-10.625,1.75) 16(-10.625,1.25) 17(-10.625,0.75) 18(-10.625,0.25) 19(-10.625,-0.25) 20(-10.625,-0.75) 21(-10.625,-1.25) 22(-10.625,-1.75) 23(-10.625,-2.25) 24(-10.625,-2.75) 25(-10.625,-3.25) 26(-10.625,-3.75) 27(-10.625,-4.25) 28(-10.625,-4.75) 29(-10.625,-5.25) 30(-10.625,-5.75) 31(-10.625,-6.25) 32(-10.625,-6.75) 33(-10.625,-7.25) 34(-10.625,-7.75) 35(-10.625,-8.25) 36(-10.625,-8.75) 73(10.625,-8.75) 74(10.625,-8.25) 75(10.625,-7.75) 76(10.625,-7.25) 77(10.625,-6.75) 78(10.625,-6.25) 79(10.625,-5.75) 80(10.625,-5.25) 81(10.625,-4.75) 82(10.625,-4.25) 83(10.625,-3.75) 84(10.625,-3.25) 85(10.625,-2.75) 86(10.625,-2.25) 87(10.625,-1.75) 88(10.625,-1.25) 89(10.625,-0.75) 90(10.625,-0.25) 91(10.625,0.25) 92(10.625,0.75) 93(10.625,1.25) 94(10.625,1.75) 95(10.625,2.25) 96(10.625,2.75) 97(10.625,3.25) 98(10.625,3.75) 99(10.625,4.25) 100(10.625,4.75) 101(10.625,5.25) 102(10.625,5.75) 103(10.625,6.25) 104(10.625,6.75) 105(10.625,7.25) 106(10.625,7.75) 107(10.625,8.25) 108(10.625,8.75)
  rect 0.3x1.35 smd paste+0 mask+0.102: 37(-8.75,-10.625) 38(-8.25,-10.625) 39(-7.75,-10.625) 40(-7.25,-10.625) 41(-6.75,-10.625) 42(-6.25,-10.625) 43(-5.75,-10.625) 44(-5.25,-10.625) 45(-4.75,-10.625) 46(-4.25,-10.625) 47(-3.75,-10.625) 48(-3.25,-10.625) 49(-2.75,-10.625) 50(-2.25,-10.625) 51(-1.75,-10.625) 52(-1.25,-10.625) 53(-0.75,-10.625) 54(-0.25,-10.625) 55(0.25,-10.625) 56(0.75,-10.625) 57(1.25,-10.625) 58(1.75,-10.625) 59(2.25,-10.625) 60(2.75,-10.625) 61(3.25,-10.625) 62(3.75,-10.625) 63(4.25,-10.625) 64(4.75,-10.625) 65(5.25,-10.625) 66(5.75,-10.625) 67(6.25,-10.625) 68(6.75,-10.625) 69(7.25,-10.625) 70(7.75,-10.625) 71(8.25,-10.625) 72(8.75,-10.625) 109(8.75,10.625) 110(8.25,10.625) 111(7.75,10.625) 112(7.25,10.625) 113(6.75,10.625) 114(6.25,10.625) 115(5.75,10.625) 116(5.25,10.625) 117(4.75,10.625) 118(4.25,10.625) 119(3.75,10.625) 120(3.25,10.625) 121(2.75,10.625) 122(2.25,10.625) 123(1.75,10.625) 124(1.25,10.625) 125(0.75,10.625) 126(0.25,10.625) 127(-0.25,10.625) 128(-0.75,10.625) 129(-1.25,10.625) 130(-1.75,10.625) 131(-2.25,10.625) 132(-2.75,10.625) 133(-3.25,10.625) 134(-3.75,10.625) 135(-4.25,10.625) 136(-4.75,10.625) 137(-5.25,10.625) 138(-5.75,10.625) 139(-6.25,10.625) 140(-6.75,10.625) 141(-7.25,10.625) 142(-7.75,10.625) 143(-8.25,10.625) 144(-8.75,10.625)
  silkscreen extent -10.75,-8.78 8.68,9.89
OSC-SMD_4P-L5.0-W3.2-BL [mm]
  rect 2x1.4 smd paste+0 mask+0.051: 1(-2.05,-1.2) 2(2.05,-1.2) 3(2.05,1.2) 4(-2.05,1.2)
  silkscreen extent -3.46,-2.26 3.24,2.03
POWERDI-123_L2.8-W1.8-LS3.7-RD#1 [mm]
  rect 2.4x1.5 smd paste+0 mask+0.051: 1(-1.187,0)
  rect 1.05x1.5 smd paste+0 mask+0.051: 2(1.187,0)
  silkscreen extent -2,-1 1.2,1
POWERDI-123_L2.8-W1.8-LS3.7-RD#2 [mm]
  rect 2.4x1.5 smd paste+0 mask+0.051: 1(1.187,0)
  rect 1.05x1.5 smd paste+0 mask+0.051: 2(-1.187,0)
  silkscreen extent -1.2,-1 2,1
R0603 [mil]
  rect 31.75x34.02 smd paste-3937.01 mask+2: 1(-29.66,0) 2(29.65,0)
  silkscreen extent -55,-26 55,26
SB-PAD [mil]
  Top Layer region: 47.24,19.68 47.24,-19.68 16.45,-19.68 -1,0 17.05,19.68
  Top Layer region: 4.69,-19.68 -15,0 4.69,19.69 -47.24,19.68 -47.24,-19.68
  silkscreen extent -50,-23 50,23
SOD-123_L2.8-W1.8-LS3.7-RD [mm]
  rect 0.95x1.15 smd paste+0 mask+0.051: 1(1.693,0) 2(-1.693,0)
  silkscreen extent -1.41,-0.94 1.63,0.94
SOIC-8_208MIL [mm]
  oval 0.7x2.2 smd paste+0 mask+0.102: 1(-1.905,-3.4) 2(-0.635,-3.4) 3(0.635,-3.4) 4(1.905,-3.4) 5(1.905,3.4) 6(0.635,3.4) 7(-0.635,3.4) 8(-1.905,3.4)
  silkscreen extent -2.95,-3.9 2.5,1.9
SOT-23-3_L2.9-W1.3-P1.90-LS2.4-BR [mm]
  rect 1.25x0.7 smd paste+0 mask+0.051: 1(1,-0.95) 2(1,0.95) 3(-1,0)
  silkscreen extent -0.73,-1.53 0.73,1.53
SOT-23-5 [mil]
  rect 50x20 smd paste+0 mask+2: 1(-65,100) 2(-65,63) 3(-65,25) 4(35,25) 5(35,100)
  silkscreen extent -65,1 18,135
SW-SMD_4P-L6.0-W6.0-P4.50-LS9.0 [mm]
  rect 2.2x1.5 smd paste+0 mask+0.051: 1(-4.4,2.25) 2(-4.4,-2.25) 3(4.4,2.25) 4(4.4,-2.25)
  silkscreen extent -3,-3 3,3
TESTHOOK [mm]
  rect 2.3x2.3 hole 1.2 slot 1.6 at 0 deg paste+0 mask+0.051: 1(0,0)
  silkscreen extent -1.8,-1.8 1.8,1.8
USB-A-TH__USB-AF-90 [mm]
  round 1.7 hole 1.1 paste+0 mask+0.051: 1(-3.5,1.355) 2(-1,1.355) 3(1,1.355) 4(3.5,1.355)
  round 3.1 hole 2.1 paste+0 mask+0.051: SH1(7,-1.355) SH2(-7,-1.355)
  silkscreen extent -7.22,-11.51 7.22,2.49
USB_MIC_DIP [mm]
  rect 2x0.4 smd paste+0 mask+0.051: 1(0,-1.3) 2(0,-0.65) 3(0,0) 4(0,0.65) 5(0,1.3)
  oval 2x1.8 hole 0.45 slot 1.2 at 0 deg paste+0 mask+0.051: 6(-0.495,-3.6) 7(2.975,-3.6) 8(2.975,3.6) 9(-0.495,3.6)
  round 0.5 hole 0.55 slot 0.555 at 0 deg unplated paste+0 mask+0.051: MH1(0.825,2) MH2(0.825,-2)
  silkscreen extent -1.82,-3.6 5.13,3.6

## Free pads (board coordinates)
  round 125.98 hole 125.98 unplated paste+0: ""(2393.82,1662.47) ""(2393.82,4379.02) ""(3665.24,2070.36) ""(3715.24,3970.34) ""(5715.24,3370.36) ""(6685.16,1662.47) ""(6685.16,4379.02)

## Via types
v1: diameter 19.69, hole 7.87, Top Layer to Bottom Layer, tented both sides, 787 vias
v2: diameter 23.62, hole 11.81, Top Layer to Bottom Layer, tented both sides, 53 vias
v3: diameter 24, hole 12, Top Layer to Bottom Layer, tented both sides, 17 vias
v4: diameter 35.43, hole 19.69, Top Layer to Bottom Layer, tented both sides, 11 vias

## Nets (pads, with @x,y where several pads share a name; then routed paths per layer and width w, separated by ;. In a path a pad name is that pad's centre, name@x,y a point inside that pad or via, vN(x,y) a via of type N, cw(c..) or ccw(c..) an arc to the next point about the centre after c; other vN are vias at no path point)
3V3: C13.1 CN4.1 CN7.1 D1.1 D4.1 D5.1 JP3.1 R10.1 R17.1 R26.1 R27.1 R28.1 U8.8 | length 9035.5
  Top Layer w10: R10.1@2651.19,3696.36 2699.59,3696.36 2744.69,3651.36 R17.1@2856.19,3651.36 ; C13.1@2991.59,3055.07 2997.19,3055.07 v3(3056.22,3114.09)
  Top Layer w15: CN4.1@2536.59,3032.57 2584.19,2982.86 2764.69,2983.36 2836.39,3055.07 2991.59,3055.07 U8.8@2991.59,2953.36
  Top Layer w20: v4(1619.86,2114.01) 1571.89,2162.07 1571.89,3543.36 1654.29,3625.76 D5.1@1654.29,3668.57 ; v4@2083.69,2043.37 2083.69,2191.26 2128.79,2236.36 2291.19,2236.36 2361.19,2306.36 v4@2373.69,2306.36 ; v4(2373.64,2306.36) 3007.64,2306.35 3037.64,2336.35 v4(3973.64,2336.36) ; D1.1@2855.64,3877.61 JP3.1@2855.64,3739.35 2855.59,3651.86 R17.1@2856.19,3651.36
  Bottom Layer w10: R28.1@3055.39,3394.66 R26.1@3056.2,3240.28 v3(3056.22,3114.09)
  Bottom Layer w15: 4315.29,2183.1 4337.02,2161.36 4339.34,2161.36
  Bottom Layer w20: v4(1619.86,2114.01) 1690.49,2043.37 2083.69,2043.37 2137.49,1989.57 2137.49,1854.27 2084.09,1800.96 2070.89,1787.66 CN7.1@2070.89,1670.96 ; v4@2373.69,2306.36 2373.69,3670.36 2442.69,3739.36 JP3.1@2855.64,3739.35 ; 2373.69,3011.66 2394.99,3032.36 ; 2373.69,3053.66 2394.99,3032.36 ; CN4.1@2536.59,3032.36 2394.99,3032.36 ; v4@3973.69,2336.36 4264.69,2336.36 4315.29,2285.76 4315.29,2070.36 ; 4315.29,2142.31 4334.34,2161.36 4337.76,2161.36 ; 4315.29,2161.36 4477.69,2161.36 4515.29,2123.76 4515.29,2070.36
  other v4: 2083.64,2043.36
5V: CN1.1 CN4.2 CN7.2 D2.1 D3.1 D6.1 F1.1 J7.2 Q1.2 Q2.2 R33.2 R36.2 | length 11901.9
  Top Layer w10: R36.2@6364.53,2272.08 6366.49,2270.16 Q2.2@6437.19,2270.16
  Top Layer w30: v4(2037.09,1980.57) 2037.09,2199.36 2115.59,2277.86 2276.29,2277.86 2326.59,2328.16 v4(2326.64,2478.36) ; v4(2326.64,2478.36) v4(2653.64,2478.36) ; v4(2327.64,3099.36) 2569.72,3099.36 CN4.2@2636.53,3032.54 ; v4@2351.69,3802.36 F1.1@2351.69,3904.36 ; J7.2@5730.29,3170.97 6028.49,3170.97 6072.29,3127.07 6072.29,2901.36 6101.09,2872.57 6308.29,2872.57 6331.19,2900.16 R33.2@6331,2940.56 Q1.2@6426.12,2941.16 6438.29,2928.97 v4(6438.32,2801.66) 6482.89,2801.66 D2.1@6530.25,2801.65 D6.1@6530.25,2706.31 ; Q2.2@6437.19,2270.16 6437.19,2207.47 v4(6438.32,2206.32)
  Bottom Layer w15: D3.1@1981.14,1830.82 1981.09,1766.57 2019.09,1728.57 2019.09,1622.77 CN7.2@2070.89,1570.96 ; 4454.69,1609.37 4454.69,1909.37 4456.69,1911.37
  Bottom Layer w30: D3.1@1981.14,1830.82 2017.29,1830.77 2037.09,1850.57 v4(2037.09,1980.57) ; v4(2326.64,2478.36) 2326.64,3777.36 v4(2351.64,3802.36) ; v4@2653.69,2478.36 2653.69,1676.37 2732.49,1597.57 6393.79,1597.57 6487.59,1691.37 6487.59,2157.07 v4(6438.32,2206.32) ; 4456.69,1911.37 4615.29,2070.36 ; v4(6438.32,2206.32) v4(6438.32,2801.66) 6438.32,3463.45 CN1.1@6506.72,3531.84
ATLINK_5V: CN6.1 D3.2 F2.1 TP3.1 | length 3070.1
  Bottom Layer w30: D3.2@1981.14,1924.32 1981.09,1959.57 1943.99,1996.66 1661.49,1996.66 1576.39,2081.76 1576.39,4115.56 1636.89,4175.97 v2(1973.07,4176.02) 1973.09,4142.36 1992.49,4123.06 TP3.1@2055.49,4123.06
  other v1: 1939.09,4176.56
ATLK_RX: CN4.10 CN7.10 R25.1 R48.1 | length 2353.1
  Top Layer w6: v1(1756.09,2083.57) 1758.09,2081.57 v1(1758.09,1929.57) ; v2@2000.59,2081.07 v2(1998.09,2083.57) 1998.09,2292.47 2019.09,2313.47 R48.1@2019.09,2397.06
  Bottom Layer w6: CN7.10@1670.89,1570.96 1721.39,1621.57 1721.39,1892.96 v1(1758.09,1929.57) ; v1(1756.09,2083.57) v2(1998.09,2083.57) 2135.27,2083.57 2171.3,2047.54 2491.22,2047.54 2614.55,2170.86 2614.55,2554.62 2636.54,2576.61 CN4.10@2636.53,2632.54 ; CN4.10@2636.59,2632.57 R25.1@2719.19,2632.66
ATLK_TX: CN4.8 CN7.8 R24.1 R47.1 | length 2351.5
  Top Layer w6: v2(1856.09,1888.57) 1856.09,2264.16 1943.09,2351.16 R47.1@1943.09,2397.07
  Bottom Layer w6: CN7.8@1770.89,1570.96 1819.43,1619.58 1819.43,1851.91 v2(1856.09,1888.57) ; v2(1854.86,2112.01) 2138.34,2112.01 2184.3,2066.06 2472.7,2066.06 2558.2,2151.55 2558.2,2565.65 2588.93,2596.38 2588.93,2684.93 CN4.8@2636.53,2732.54 ; CN4.8@2636.59,2732.57 2719.29,2732.57 R24.1@2719.39,2732.66
B2_2: B2.2 B2.4 R18.2 R19.1 | length 568
  Top Layer w6: B2.4@2403.39,2025.96 2749.89,2025.96 2827.69,2025.96 R18.2@2854.14,2052.35 2853.09,2053.36 R19.1@2853.14,2158.35
BOOT0: CN4.4 CN7.4 J1.66 R13.2 R45.1 U1.138 | length 5742.7
  Top Layer w6: R45.1@1794.09,2397.07 1794.09,1895.57 1953.69,1735.96 1979.39,1735.96 2021.49,1693.96 2021.49,1621.57 CN7.4@1970.89,1570.96 ; v1(2487.64,2542.36) 2549.49,2542.36 2588.54,2581.41 2588.54,2884.54 CN4.4@2636.53,2932.54 ; v1(2689.09,3130.99) 2732.01,3130.99 v1(2759.96,3130.99) ; J1.66@3204.59,4169.56 3204.59,3771.36 v1(3299.69,3676.36) 4367.29,3676.36 4439.29,3604.36 U1.138@4439.31,3512.68
  Bottom Layer w6: v2(1793.64,2186.36) 2123.64,2186.36 2228.64,2081.35 2451.64,2081.35 2487.64,2117.35 v1(2487.64,2542.36) ; CN4.4@2636.53,2932.54 2759.96,3055.95 v1(2759.96,3130.99) ; R13.2@2647.19,3132.36 2648.49,3130.97 v1(2689.09,3130.99) ; v1(2759.96,3130.99) 2759.99,3357.66 2766.59,3364.26 2766.59,3476.57 2859.99,3569.97 3193.29,3569.97 v1(3299.69,3676.36)
C5_1: C5.1 C6.1 F1.2 U2.1 U2.3 | length 369.5
  Top Layer w6: U2.1@2546.59,3968.97 2589.99,3968.97 2601.69,3957.36 2601.69,3907.36 2589.59,3895.36 U2.3@2559.69,3895.36
  Top Layer w30: F1.2@2351.69,3963.66 2353.79,3961.47 2466.69,3961.47 2493.29,3961.47 2502.09,3970.36 U2.1@2559.69,3970.36
C7_1: C7.1 D1.2 R16.2 U2.5 | length 196.6
  Top Layer w20: U2.5@2659.69,3970.36 2690.19,3970.36 2690.59,3969.86 R16.2@2725.64,3969.85 2726.89,3971.07 D1.2@2855.64,3971.11
CN3_2: CN3.2 R40.2 | length 182.5
  Top Layer w6: R40.2@6632.79,2461.36 6683.39,2462.36 6697.79,2476.76 CN3.2@6809.29,2476.76
CN3_3: CN3.3 R39.2 | length 180.2
  Top Layer w6: R39.2@6632.79,2511.36 6696.29,2511.36 6705.29,2502.36 CN3.3@6809.29,2502.36
CN3_4: CN3.4 R38.2 | length 190.3
  Top Layer w6: R38.2@6632.79,2561.36 6670.29,2561.36 6703.79,2527.97 CN3.4@6809.29,2527.97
